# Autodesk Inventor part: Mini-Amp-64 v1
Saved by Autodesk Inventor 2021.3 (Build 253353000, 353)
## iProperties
Created: 2022-07
Part Number: Mini-Amp-64 v1
Material: Generic
Document SubType Name: Modeling
Designer: Administrator
Density: 1 g/cm^3
Appearance: Default
Title: Mini-Amp-64 v1
Author: Administrator
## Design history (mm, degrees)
